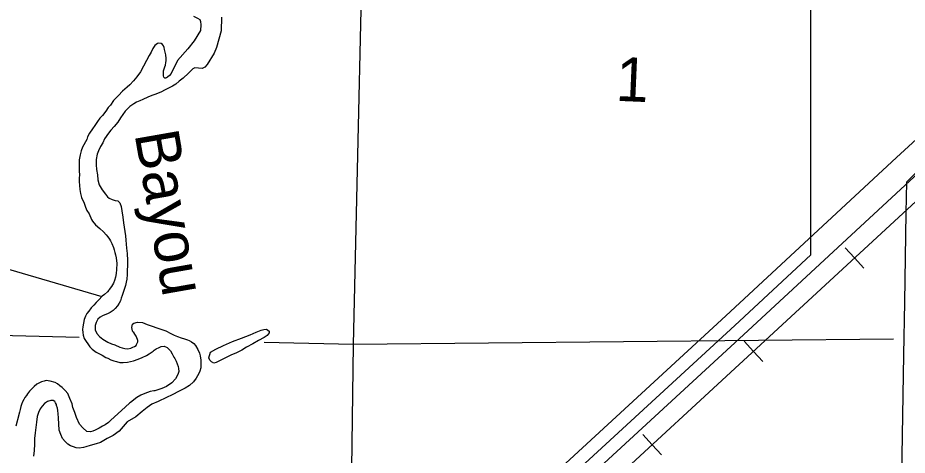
# Model space of a CAD drawing. Extents: x 1196286 to 1268366, y 2040822 to 2082115.
# Drawn here: x 1235560 to 1238759, y 2062866 to 2064439 of the extents above; entities that cross this region are included whole.
import ezdxf

# ---------------------------------------------------------------- set-up
doc = ezdxf.new("R2010")
doc.units = 0
for name, color, linetype in [('60', 7, 'Continuous'), ('62', 7, 'Continuous'), ('Level 74', 7, 'Continuous'), ('Level 8', 7, 'Continuous'), ('Level 81', 7, 'Continuous'), ('Level 84', 7, 'Continuous'), ('Level 87', 7, 'Continuous')]:
    doc.layers.add(name, color=color, linetype=linetype)

msp = doc.modelspace()

# ---------------------------------------------------------------- linework, layer by layer
at = {"layer": '60'}
for points in [[(1236756.7, 2062461.7), (1236767.5, 2063263.5), (1236812.2, 2065202)], [(1235781.1, 2063288.7), (1235444.4, 2063297.2)], [(1238709.7, 2063283), (1236767.5, 2063263.5), (1236446.8, 2063271.7)]]:
    msp.add_lwpolyline(points, dxfattribs=at)
at = {"layer": '62'}
for points in [[(1236192.3, 2064444.9), (1236206.8, 2064438.2), (1236214.9, 2064432.4), (1236217.7, 2064425.5), (1236219, 2064413.4), (1236217.4, 2064393.2), (1236194.5, 2064355.6), (1236171.4, 2064327.5), (1236134.1, 2064285)], [(1236293, 2064440.9), (1236292, 2064392.7), (1236274.9, 2064332.1), (1236266.2, 2064311.6), (1236241.7, 2064271.1), (1236232.9, 2064261.1), (1236223.8, 2064256.4), (1236196.9, 2064258.8), (1236189.3, 2064254.9), (1236174.3, 2064239.7)], [(1236134.1, 2064285), (1236111.7, 2064239.2), (1236105.6, 2064231.8), (1236099.1, 2064225.1), (1236095.4, 2064222.9), (1236091.6, 2064222.5), (1236089.4, 2064222.2), (1236086, 2064225.6), (1236084.2, 2064230.1), (1236084.3, 2064237.3), (1236084, 2064242.9), (1236084.8, 2064248.5), (1236086.7, 2064255.3), (1236089.4, 2064262.8), (1236091.4, 2064269.2), (1236092.6, 2064277.8), (1236093.4, 2064284.2), (1236093.9, 2064293.2), (1236092.6, 2064306.4), (1236090.4, 2064315.4), (1236088.3, 2064325.2), (1236086.8, 2064332), (1236084.3, 2064337.7), (1236080.2, 2064342.6), (1236076.1, 2064346.4), (1236067.9, 2064347.7), (1236063, 2064346.6), (1236053.2, 2064339.2), (1236046, 2064328.7), (1236039.8, 2064316), (1236033.3, 2064302.9), (1236022.6, 2064285), (1236012.7, 2064265.5), (1236001.6, 2064244.9), (1235988.6, 2064227), (1235976.9, 2064212.8), (1235963.2, 2064197.9), (1235953.4, 2064189.4), (1235936.7, 2064175.7), (1235921.9, 2064160), (1235904.9, 2064141), (1235893.1, 2064125), (1235885.5, 2064116.4), (1235876.7, 2064103.7), (1235864.9, 2064088), (1235855.8, 2064078), (1235847.5, 2064066.4), (1235837.9, 2064052.2), (1235828.4, 2064039.9), (1235818.5, 2064024.2), (1235811.2, 2064010.4), (1235808.1, 2064001), (1235793.2, 2063973.3), (1235787.8, 2063960.2), (1235784.7, 2063946.3), (1235780.7, 2063927.9), (1235780.6, 2063917), (1235781.2, 2063904.6), (1235781.4, 2063887.7), (1235782, 2063873.8), (1235781.1, 2063861.7), (1235781.4, 2063850.4), (1235781.9, 2063835.4), (1235783.3, 2063821.5), (1235785.8, 2063807.1), (1235789.7, 2063792.4), (1235798.5, 2063772), (1235803.2, 2063758), (1235809.1, 2063746.3), (1235816.8, 2063733.4), (1235825.6, 2063713.8), (1235828.9, 2063708.1), (1235840, 2063694.8), (1235855.2, 2063680.7), (1235868.5, 2063669.7), (1235878.2, 2063658.7), (1235884.1, 2063651.8), (1235889.6, 2063642.8), (1235894, 2063637.4), (1235898.8, 2063627.2), (1235904.6, 2063612.5), (1235907.2, 2063604.6), (1235909.7, 2063594.4), (1235912.2, 2063586.5), (1235914.3, 2063575.2), (1235915.4, 2063564.6), (1235916.4, 2063556.7), (1235916.3, 2063549.2), (1235915.8, 2063539.4), (1235915.4, 2063532.3), (1235914.1, 2063521), (1235912.9, 2063512.3), (1235911.7, 2063506.3), (1235907.8, 2063494), (1235904, 2063485), (1235897.8, 2063472.6), (1235888.7, 2063462.2), (1235887.6, 2063460), (1235882.3, 2063452.9), (1235872, 2063443.9), (1235863.7, 2063437.6)], [(1236174.3, 2064239.7), (1236154.9, 2064221.8), (1236141, 2064211.5), (1236129.2, 2064199.9), (1236117.2, 2064192.9), (1236107, 2064188.9), (1236088.1, 2064178.5), (1236076.8, 2064172.3), (1236056.5, 2064164.2), (1236042.2, 2064159.9), (1236027.5, 2064154), (1236009.8, 2064145.5), (1235998.9, 2064140.8), (1235987.6, 2064135.6), (1235977.8, 2064129.3), (1235963.5, 2064120.5), (1235955.9, 2064113.4), (1235946, 2064103.3), (1235937.7, 2064091.8), (1235929.3, 2064079.4), (1235919.7, 2064064.1), (1235906.8, 2064047.7), (1235895.1, 2064034.3), (1235886.7, 2064023.5), (1235872.6, 2064003.7), (1235865.7, 2063989.8), (1235857.3, 2063976), (1235850, 2063961.1), (1235845.8, 2063949.1), (1235842.6, 2063928.8), (1235842.4, 2063910.7), (1235843.7, 2063893.8), (1235847.2, 2063874.6), (1235848.5, 2063856.5), (1235853.5, 2063838.4), (1235863.5, 2063820.6), (1235875.3, 2063805), (1235882.7, 2063795.6), (1235889, 2063790.6), (1235899.1, 2063785.6), (1235911, 2063782.5), (1235920, 2063780.9), (1235927.8, 2063774), (1235932.5, 2063760.4), (1235935, 2063744.6), (1235938.4, 2063721.6), (1235940.5, 2063702), (1235948.2, 2063654.5), (1235949.1, 2063638.7), (1235951.8, 2063610.1), (1235953.1, 2063590.9), (1235954.3, 2063566.4), (1235954.5, 2063548.4), (1235953.6, 2063530.7), (1235953.4, 2063516), (1235952.1, 2063499.1), (1235950.5, 2063488.2), (1235947.3, 2063475.9), (1235943.1, 2063462.4), (1235939.2, 2063451.5), (1235935.3, 2063440.3), (1235932.2, 2063430.5), (1235929.1, 2063421.1), (1235924.9, 2063412.9), (1235918.4, 2063402.8), (1235910.8, 2063393.5), (1235903.3, 2063386.8), (1235891.9, 2063379), (1235882.9, 2063373.9), (1235873.9, 2063370.6), (1235865.2, 2063366.5), (1235856.2, 2063362.5), (1235848.6, 2063355), (1235842.1, 2063343.1), (1235839, 2063332.2), (1235838.8, 2063317.2), (1235845, 2063303.5), (1235854.3, 2063292.9), (1235865.8, 2063283), (1235883.6, 2063272.7), (1235897.1, 2063266.9), (1235909, 2063262.2), (1235927.7, 2063254.9), (1235935.5, 2063252.2), (1235944.8, 2063249.4), (1235956.5, 2063248.9), (1235966.6, 2063250.3), (1235973.8, 2063254), (1235980.5, 2063257.3), (1235985.8, 2063260.6), (1235987.7, 2063263.6), (1235992, 2063273.4), (1235992, 2063278.3), (1235991.3, 2063282), (1235985.4, 2063294.1), (1235981, 2063300.9), (1235977.3, 2063306.6), (1235974.4, 2063309.7), (1235972.5, 2063313.1), (1235971.1, 2063319.5), (1235970.4, 2063325.5)], [(1235863.7, 2063437.6), (1235851.6, 2063425), (1235841.7, 2063414.6), (1235833.4, 2063405.2), (1235824.3, 2063396.3), (1235815.2, 2063384.4), (1235808.7, 2063375.8), (1235803.7, 2063365.7), (1235799.1, 2063354.5), (1235796, 2063341.3), (1235793.9, 2063327), (1235793.1, 2063317.7), (1235793.7, 2063307.1), (1235795.5, 2063297.7), (1235798.7, 2063285.6), (1235819.4, 2063256.1), (1235827.5, 2063247.3), (1235841.7, 2063237), (1235854.3, 2063230.1), (1235863.3, 2063225.5), (1235877, 2063217.8), (1235884.5, 2063214.3), (1235895.3, 2063209.3), (1235905.8, 2063204.7), (1235914.7, 2063202.7), (1235927.4, 2063198.8), (1235939, 2063198.7), (1235954.8, 2063200), (1235975.8, 2063205.5), (1235992.8, 2063211.3), (1236007.4, 2063217.2), (1236022.9, 2063224.5), (1236032.7, 2063230.8), (1236047, 2063240), (1236050.8, 2063244.1), (1236058.4, 2063249), (1236068.6, 2063253.7), (1236075.7, 2063256.7), (1236087, 2063257.7), (1236097.4, 2063253), (1236110, 2063240.9), (1236115.1, 2063230.3), (1236121.8, 2063218.6), (1236125.1, 2063213.6), (1236130.2, 2063203.8), (1236133.8, 2063194), (1236137.1, 2063184.5), (1236138.5, 2063178.1), (1236139.2, 2063166.5), (1236137.6, 2063159.3), (1236132.2, 2063148.8), (1236127.3, 2063140.2), (1236114, 2063125.7), (1236094.7, 2063112.8), (1236077.8, 2063105.4), (1236052.6, 2063097.8), (1236049.6, 2063097.4), (1236036.8, 2063094.6), (1236017.3, 2063087.6), (1236003, 2063082.2), (1235987.9, 2063072.9), (1235965.6, 2063055.5), (1235961.8, 2063052.5), (1235948.2, 2063039.9), (1235894, 2062990.8), (1235886.1, 2062983.7), (1235874.7, 2062974.8), (1235865.3, 2062970), (1235852.5, 2062962.7), (1235838.9, 2062955.3), (1235830.3, 2062952), (1235821.2, 2062949.8), (1235808.5, 2062951.5), (1235794.4, 2062963.7), (1235782.2, 2062977.7), (1235770.9, 2063001.9), (1235765.1, 2063019.6), (1235758.5, 2063037), (1235755.3, 2063051), (1235748, 2063069.9), (1235740.3, 2063087.2), (1235731.1, 2063099), (1235719.6, 2063109.7), (1235711.8, 2063115.8), (1235702.9, 2063122.3), (1235694.3, 2063127.2), (1235677.1, 2063131.9), (1235669.3, 2063133.5), (1235661.8, 2063134), (1235654.6, 2063132.6), (1235645.6, 2063129.3), (1235635.4, 2063125.2), (1235628.3, 2063120.8), (1235619.2, 2063113.4), (1235611.6, 2063105.9), (1235602.9, 2063096.6), (1235595.7, 2063086.9), (1235591.5, 2063080.6), (1235586.2, 2063073.5), (1235581.6, 2063066.4), (1235577, 2063057.4)], [(1235970.4, 2063325.5), (1235972.4, 2063337.2), (1235977.3, 2063341.2), (1235991.2, 2063344.9), (1236008.5, 2063343.2), (1236025.2, 2063335.5), (1236078.6, 2063318.3), (1236093.2, 2063312.9), (1236110.7, 2063303.7), (1236123, 2063297.5), (1236134.6, 2063292.5), (1236147.3, 2063288.2), (1236159.2, 2063284.7), (1236170.8, 2063280.5), (1236176, 2063278.5), (1236184.6, 2063273.5), (1236193.9, 2063267.1), (1236199.4, 2063260.6), (1236208.2, 2063245.8), (1236213.3, 2063232.6), (1236216.6, 2063222.8), (1236218.7, 2063207.3), (1236218.9, 2063193.8), (1236218.4, 2063180.3), (1236214.9, 2063168.6), (1236211.4, 2063159.3), (1236201.9, 2063142.5), (1236192.3, 2063130.1), (1236178, 2063116), (1236162.5, 2063106.8), (1236140.3, 2063095.7), (1236115, 2063083.2), (1236095, 2063073.6), (1236064.5, 2063059.3), (1236041.9, 2063049.8), (1236025.7, 2063037.9), (1236007.5, 2063023), (1235984.5, 2063003.7), (1235953.9, 2062985.3), (1235924.3, 2062952.5), (1235902.8, 2062936.9), (1235882.1, 2062925.5), (1235858.3, 2062911.8), (1235842.5, 2062906.7), (1235820.3, 2062900.9), (1235804.5, 2062895.8), (1235797, 2062893.7), (1235781.6, 2062891.6), (1235770.4, 2062892.4), (1235760.3, 2062895.6), (1235749.5, 2062899.8), (1235740.6, 2062905.2), (1235730.2, 2062915.1), (1235721.3, 2062925.7), (1235715.1, 2062940.4), (1235708.9, 2062956.3), (1235707.1, 2063000.7), (1235705.8, 2063014.6), (1235704.8, 2063027.1), (1235702.6, 2063034.6), (1235699.8, 2063044.1), (1235699, 2063048.2), (1235696.5, 2063053.9), (1235693.2, 2063058.8), (1235687.2, 2063062.2), (1235679, 2063062.3), (1235667.3, 2063059.1), (1235656.4, 2063052), (1235647.6, 2063041.6), (1235641.2, 2063032.3), (1235634.3, 2063019.9), (1235630, 2063004.6), (1235627.9, 2062984.3), (1235624.7, 2062965.5), (1235622.2, 2062946), (1235620.5, 2062926), (1235620.6, 2062905.3), (1235618.9, 2062882.8), (1235616.8, 2062862.9)], [(1236329.2, 2063227.2), (1236273.3, 2063198.9), (1236265.4, 2063197.4), (1236256.8, 2063201.7), (1236250.5, 2063208.1), (1236246.9, 2063215.7), (1236253.5, 2063235.9), (1236272.3, 2063247), (1236300.2, 2063260.6), (1236331.8, 2063274.6), (1236365.3, 2063287), (1236396.2, 2063298.3), (1236417.7, 2063308.3), (1236435.3, 2063315.6), (1236444.7, 2063318.1), (1236455.2, 2063318.8), (1236464.2, 2063312.3), (1236464.5, 2063305.9), (1236457.2, 2063295.8), (1236446.3, 2063289.2), (1236425.6, 2063278.8), (1236405.2, 2063266.3), (1236383.3, 2063254.8), (1236365.6, 2063243.4), (1236344.9, 2063233), (1236329.2, 2063227.2)], [(1235577, 2063057.4), (1235573.5, 2063048), (1235571.6, 2063040.9), (1235568.8, 2063030), (1235566.8, 2063021), (1235564.5, 2063012), (1235564.1, 2063010.7)], [(1235564.1, 2063010.7), (1235553.4, 2062970.1)]]:
    msp.add_lwpolyline(points, dxfattribs=at)
at = {"layer": 'Level 74'}
msp.add_lwpolyline([(1235240.3, 2063436.3), (1235314.6, 2063458.2), (1235340.2, 2063473.5), (1235365.9, 2063493), (1235384.1, 2063512), (1235397.6, 2063523.2), (1235412.6, 2063536.2), (1235424.9, 2063545.6), (1235437.8, 2063551.2), (1235449.9, 2063555.3), (1235456.7, 2063555.1), (1235863.1, 2063436.9)], dxfattribs=at)
at = {"layer": 'Level 8'}
msp.add_line((1238412.5, 2063586.9), (1238412.5, 2069077.4), dxfattribs=at)
msp.add_lwpolyline([(1236659.6, 2061971.8), (1237061.2, 2062341), (1238138.5, 2063332.8), (1238412.5, 2063586.9)], dxfattribs=at)
at = {"layer": 'Level 81'}
for p, q in [((1238569.5, 2063575.2), (1238535.9, 2063611.6)), ((1238569.5, 2063575.2), (1238603, 2063538.8)), ((1238205.7, 2063239.4), (1238172.2, 2063275.8)), ((1238205.7, 2063239.4), (1238239.3, 2063203.1)), ((1237842, 2062903.7), (1237808.4, 2062940.1)), ((1237842, 2062903.7), (1237875.6, 2062867.3))]:
    msp.add_line(p, q, dxfattribs=at)
msp.add_lwpolyline([(1240757.7, 2065596.8), (1240486.9, 2065346.1), (1239022.5, 2063993.4), (1236837.6, 2061976.6), (1235905.3, 2061125.6), (1235621.7, 2060865.7), (1235429, 2060684.3)], dxfattribs=at)
msp.add_lwpolyline([(1240757.7, 2065596.8), (1240486.9, 2065346.1), (1239022.5, 2063993.4), (1236837.6, 2061976.6), (1235905.3, 2061125.6), (1235621.7, 2060865.7), (1235429, 2060684.3)], dxfattribs=at)
msp.add_lwpolyline([(1240757.7, 2065596.8), (1240486.9, 2065346.1), (1239022.5, 2063993.4), (1236837.6, 2061976.6), (1235905.3, 2061125.6), (1235621.7, 2060865.7), (1235429, 2060684.3)], dxfattribs=at)
at = {"layer": 'Level 84'}
for points in [[(1239200, 2064377.2), (1239159, 2064337.3), (1239047, 2064234.7), (1238877.3, 2064081), (1238720.3, 2063936.3), (1238106.7, 2063367.3), (1237029.5, 2062375.5), (1236487.9, 2061877.6)], [(1236551.3, 2061808.6), (1237092.9, 2062306.5), (1238170.3, 2063298.4), (1238783.9, 2063867.4), (1238940.5, 2064011.8), (1239110.1, 2064165.4), (1239223.3, 2064269.1), (1239265.3, 2064309.9)]]:
    msp.add_lwpolyline(points, dxfattribs=at)
at = {"layer": 'Level 87'}
for p, q in [((1238853.5, 2063946.7), (1238756.2, 2063847.6)), ((1238756.2, 2063847.6), (1238754.2, 2063737.6)), ((1238754.2, 2063737.6), (1238748.3, 2063415.8)), ((1238748.3, 2063415.8), (1238744.9, 2063226.9)), ((1238744.9, 2063226.9), (1238733.4, 2062548.8))]:
    msp.add_line(p, q, dxfattribs=at)

# ---------------------------------------------------------------- texts
at = {"layer": '60'}
msp.add_text('1', height=158.4, rotation=357.548, dxfattribs=at).set_placement((1237708.6, 2064140.7))
at = {"layer": '62'}
msp.add_text('Bayou', height=158.4, rotation=279.9529, dxfattribs=at).set_placement((1235979.7, 2064021.5))

doc.saveas('drawing.dxf')
